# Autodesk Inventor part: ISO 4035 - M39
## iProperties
IsCustomPart: 0
Created: 2009-02
Part Number: ISO 4035 - M39
Material: Stainless Steel, 440C
Description: Hexagon thin nuts (chamfered) - Product grades A and B
Document SubType Name: Modeling
Standard: ISO 4035
Designer: 904Chiaki
Standard Revision: Third edition 1999-08-15
Standards Organization: ISO
Language: en-US
Size Designation: M39
Categories: <MemberInstance><Categories><Category DisplayName="Fasteners" InternalName="e4da775c-781d-43d5-af7c-5136215cf5a6" Mnemonic="FSTN"><Category DisplayName="Nuts" I
Density: 7.75 g/cm^3
Author: 904Chiaki
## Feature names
1. Body [Extrusion]
2. Chamfer1 [Revolution]
3. Thread [Hole]
4. Chamfer2
5. Chamfer3
